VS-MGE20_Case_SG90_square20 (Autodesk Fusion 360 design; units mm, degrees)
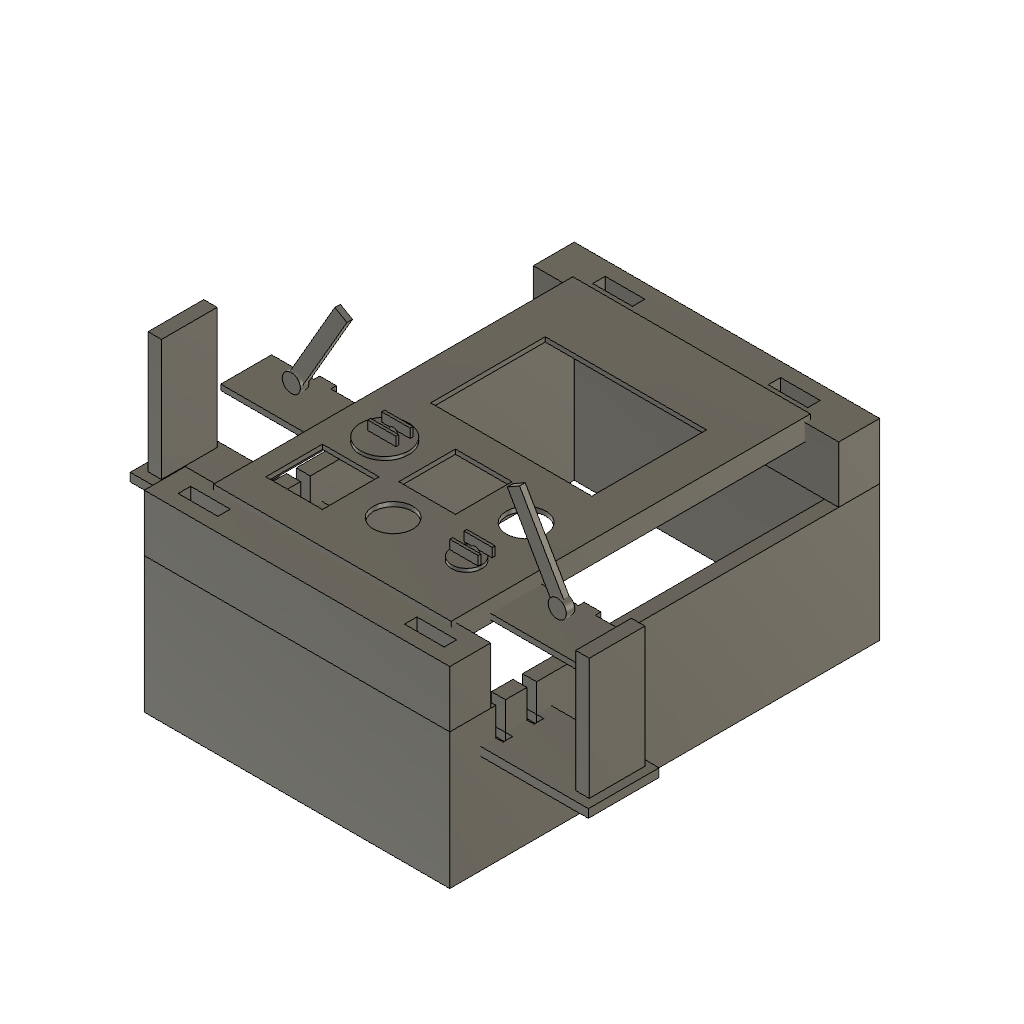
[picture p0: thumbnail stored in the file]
sketch "スケッチ1" plane through (0, 0, 0) normal (0, 0, 1) x axis (1, 0, 0)
  line L1 (42, -63.5) -> (-42, -63.5)
  line L2 (42, 63.5) -> (42, -63.5)
  line L3 (-42, 63.5) -> (42, 63.5)
  line L4 (-42, -63.5) -> (-42, 63.5)
  line L5 (28.5, -0.25) -> (-28.5, -0.25)
  line L6 (28.5, 40.25) -> (28.5, -0.25)
  line L7 (-28.5, 40.25) -> (28.5, 40.25)
  line L8 (-28.5, -0.25) -> (-28.5, 40.25)
  line L9 (-16, -34.55) -> (-33, -34.55)
  line L10 (-16, -33.45) -> (-16, -34.55)
  line L11 (-33, -33.45) -> (-16, -33.45)
  line L12 (-33, -34.55) -> (-33, -33.45)
  line L13 (-16, -37.55) -> (-33, -37.55)
  line L14 (-16, -36.45) -> (-16, -37.55)
  line L15 (-33, -36.45) -> (-16, -36.45)
  line L16 (-33, -37.55) -> (-33, -36.45)
  line L17 (-16, -40.55) -> (-33, -40.55)
  line L18 (-16, -39.45) -> (-16, -40.55)
  line L19 (-33, -39.45) -> (-16, -39.45)
  line L20 (-33, -40.55) -> (-33, -39.45)
  line L21 (-16, -43.55) -> (-33, -43.55)
  line L22 (-16, -42.45) -> (-16, -43.55)
  line L23 (-33, -42.45) -> (-16, -42.45)
  line L24 (-33, -43.55) -> (-33, -42.45)
  line L25 (-16, -46.55) -> (-33, -46.55)
  line L26 (-16, -45.45) -> (-16, -46.55)
  line L27 (-33, -45.45) -> (-16, -45.45)
  line L28 (-33, -46.55) -> (-33, -45.45)
  line L29 (-16, -49.55) -> (-33, -49.55)
  line L30 (-16, -48.45) -> (-16, -49.55)
  line L31 (-33, -48.45) -> (-16, -48.45)
  line L32 (-33, -49.55) -> (-33, -48.45)
  circle C1 centre (-25, -20) radius 8
  circle C2 centre (26, -42) radius 4.8
extrude "押し出し1" new body sketch "スケッチ1" along normal blind 1.6
sketch "スケッチ2" plane through (0, 0, 0) normal (0, 0, 1) x axis (1, 0, 0)
  line L1 (42, -63.5) -> (-42, -63.5)
  line L2 (42, 63.5) -> (42, -63.5)
  line L3 (-42, 63.5) -> (42, 63.5)
  line L4 (-42, -63.5) -> (-42, 63.5)
  line L5 (40.5, -62) -> (-40.5, -62)
  line L6 (40.5, 62) -> (40.5, -62)
  line L7 (-40.5, 62) -> (40.5, 62)
  line L8 (-40.5, -62) -> (-40.5, 62)
extrude "押し出し4" add sketch "スケッチ2" against normal blind 6 (magnitude of "-( 6.00 mm )")
work_plane "作業平面1" AlongDistance -68 ExtraOffset 0
sketch "スケッチ3" plane through (0, 0, -68) normal (0, 0, 1) x axis (1, 0, 0)
  line L1 (54, -76) -> (-54, -76)
  line L2 (54, 76) -> (54, -76)
  line L3 (-54, 76) -> (54, 76)
  line L4 (-54, -76) -> (-54, 76)
  line L5 (49, -71) -> (-49, -71)
  line L6 (49, 71) -> (49, -71)
  line L7 (-49, 71) -> (49, 71)
  line L8 (-49, -71) -> (-49, 71)
work_plane "作業平面2" AlongDistance -20 ExtraOffset 0
sketch "スケッチ4" plane through (0, 0, -20) normal (0, 0, 1) x axis (1, 0, 0)
  line L1 (54, 61.5) -> (-54, 61.5)
  line L2 (54, 76) -> (54, 61.5)
  line L3 (-54, 76) -> (54, 76)
  line L4 (-54, 61.5) -> (-54, 76)
  line L5 (54, -76) -> (-54, -76)
  line L6 (54, -61.5) -> (54, -76)
  line L7 (-54, -61.5) -> (54, -61.5)
  line L8 (-54, -76) -> (-54, -61.5)
extrude "押し出し6" new body sketch "スケッチ4" profile of L1 L2 L3 L4 along normal blind 20
work_plane "作業平面3" AlongDistance -23 ExtraOffset 0
sketch "スケッチ5" plane through (0, 0, -23) normal (0, 0, 1) x axis (1, 0, 0)
  line L1 (-44, -24) -> (-90, -24)
  line L2 (-44, 28) -> (-44, -24)
  line L3 (-90, 28) -> (-44, 28)
  line L4 (-90, -24) -> (-90, 28)
  line L5 (90, -46) -> (44, -46)
  line L6 (90, 6) -> (90, -46)
  line L7 (44, 6) -> (90, 6)
  line L8 (44, -46) -> (44, 6)
  circle C1 centre (-84, -18) radius 1.7
  circle C2 centre (-50, 20) radius 1.7
  circle C3 centre (-84, -56) radius 1.7
  circle C4 centre (-50, -22) radius 1.7
  circle C5 centre (84, -40) radius 1.7
  circle C6 centre (50, 2) radius 1.7
  circle C7 centre (84, -78) radius 1.7
  circle C8 centre (50, -44) radius 1.7
work_plane "作業平面4" AlongDistance -20 ExtraOffset 0
sketch "スケッチ6" plane through (0, 0, -20) normal (0, 0, 1) x axis (1, 0, 0)
  line L1 (54, -76) -> (-54, -76)
  line L2 (54, -61.5) -> (54, -76)
  line L3 (-54, -61.5) -> (54, -61.5)
  line L4 (-54, -76) -> (-54, -61.5)
work_plane "作業平面5" AlongDistance -23 ExtraOffset 0
sketch "スケッチ7" plane through (0, 0, -23) normal (0, 0, 1) x axis (1, 0, 0)
  line L1 (90, -46) -> (44, -46)
  line L2 (90, 6) -> (90, -46)
  line L3 (44, 6) -> (90, 6)
  line L4 (44, -46) -> (44, 6)
  circle C1 centre (84, -40) radius 1.7
  circle C2 centre (50, 2) radius 1.7
  circle C3 centre (84, -78) radius 1.7
  circle C4 centre (50, -44) radius 1.7
work_plane "作業平面6" AlongDistance -19.7 ExtraOffset 0
sketch "スケッチ8" plane through (0, 0, -19.7) normal (0, 0, 1) x axis (1, 0, 0)
  line L1 (-46.65, -20) -> (-87.35, -20)
  line L2 (-46.65, 22.9) -> (-46.65, -20)
  line L3 (-87.35, 22.9) -> (-46.65, 22.9)
  line L4 (-87.35, -20) -> (-87.35, 22.9)
work_plane "作業平面7" AlongDistance -19.7 ExtraOffset 0
sketch "スケッチ9" plane through (0, 0, -19.7) normal (0, 0, 1) x axis (1, 0, 0)
  line L1 (87.35, -42) -> (46.65, -42)
  line L2 (87.35, 0.9) -> (87.35, -42)
  line L3 (46.65, 0.9) -> (87.35, 0.9)
  line L4 (46.65, -42) -> (46.65, 0.9)
work_plane "作業平面8" AlongDistance 18 ExtraOffset 0
sketch "スケッチ10" plane through (0, 18, 0) normal (0, 1, 0) x axis (1, 0, 0)
  line L1 (-25.3119, 0.9501) -> (-55.3119, -8.8999)
  line L2 (-24.6881, -0.9501) -> (-25.3119, 0.9501)
  line L3 (-54.6881, -10.8001) -> (-24.6881, -0.9501)
  line L4 (-55.3119, -8.8999) -> (-54.6881, -10.8001)
work_plane "作業平面9" AlongDistance 40 ExtraOffset 0
sketch "スケッチ11" plane through (0, 40, 0) normal (0, 1, 0) x axis (1, 0, 0)
  line L1 (25.6784, -0.9469) -> (54.6784, -10.7969)
  line L2 (26.3216, 0.9469) -> (25.6784, -0.9469)
  line L3 (55.3216, -8.9031) -> (26.3216, 0.9469)
  line L4 (54.6784, -10.7969) -> (55.3216, -8.9031)
work_plane "作業平面10" AlongDistance -0.3 ExtraOffset 0
sketch "スケッチ12" plane through (0, 0, -0.3) normal (0, 0, 1) x axis (1, 0, 0)
  circle C1 centre (-25, -20) radius 3.5
  circle C2 centre (26, -42) radius 2.8
work_plane "作業平面11" AlongDistance 1.6 ExtraOffset 0
sketch "スケッチ13" plane through (0, 0, 1.6) normal (0, 0, 1) x axis (1, 0, 0)
  line L1 (-24.6696, -17.5219) -> (-54.6696, -13.5219)
  line L2 (-25.3304, -22.4781) -> (-24.6696, -17.5219)
  line L3 (-55.3304, -18.4781) -> (-25.3304, -22.4781)
  line L4 (-54.6696, -13.5219) -> (-55.3304, -18.4781)
  line L5 (26.3416, -44.4766) -> (55.3416, -40.4766)
  line L6 (25.6584, -39.5234) -> (26.3416, -44.4766)
  line L7 (54.6584, -35.5234) -> (25.6584, -39.5234)
  line L8 (55.3416, -40.4766) -> (54.6584, -35.5234)
work_plane "作業平面12" AlongDistance 0 ExtraOffset 0
sketch "スケッチ14" plane through (0, 0, 0) normal (0, 0, 1) x axis (1, 0, 0)
  circle C1 centre (-55, -16) radius 4.2
  circle C2 centre (55, -38) radius 4.2
work_plane "作業平面13" AlongDistance -0.3 ExtraOffset 0
sketch "スケッチ15" plane through (0, 0, -0.3) normal (0, 0, 1) x axis (1, 0, 0)
  circle C1 centre (-25, -20) radius 3.5
  circle C2 centre (26, -42) radius 2.8
work_plane "作業平面14" AlongDistance -20 ExtraOffset 0
sketch "スケッチ16" plane through (0, 0, -20) normal (0, 0, 1) x axis (1, 0, 0)
  line L1 (-24, -70.95) -> (-38, -70.95)
  line L2 (-24, -66.55) -> (-24, -70.95)
  line L3 (-38, -66.55) -> (-24, -66.55)
  line L4 (-38, -70.95) -> (-38, -66.55)
  line L5 (38, -70.95) -> (24, -70.95)
  line L6 (38, -66.55) -> (38, -70.95)
  line L7 (24, -66.55) -> (38, -66.55)
  line L8 (24, -70.95) -> (24, -66.55)
  line L9 (-24, 66.55) -> (-38, 66.55)
  line L10 (-24, 70.95) -> (-24, 66.55)
  line L11 (-38, 70.95) -> (-24, 70.95)
  line L12 (-38, 66.55) -> (-38, 70.95)
  line L13 (38, 66.55) -> (24, 66.55)
  line L14 (38, 70.95) -> (38, 66.55)
  line L15 (24, 70.95) -> (38, 70.95)
  line L16 (24, 66.55) -> (24, 70.95)
work_plane "作業平面15" AlongDistance 1.6 ExtraOffset 0
sketch "スケッチ17" plane through (0, 0, 1.6) normal (0, 0, 1) x axis (1, 0, 0)
  line L1 (26.3416, -44.4766) -> (55.3416, -40.4766)
  line L2 (25.6584, -39.5234) -> (26.3416, -44.4766)
  line L3 (54.6584, -35.5234) -> (25.6584, -39.5234)
  line L4 (55.3416, -40.4766) -> (54.6584, -35.5234)
work_plane "作業平面16" AlongDistance 0 ExtraOffset 0
sketch "スケッチ18" plane through (0, 0, 0) normal (0, 0, 1) x axis (1, 0, 0)
  circle C1 centre (55, -38) radius 4.2
work_plane "作業平面17" AlongDistance -0.3 ExtraOffset 0
sketch "スケッチ19" plane through (0, 0, -0.3) normal (0, 0, 1) x axis (1, 0, 0)
  circle C1 centre (26, -42) radius 2.8
work_plane "作業平面18" AlongDistance -20 ExtraOffset 0
sketch "スケッチ20" plane through (0, 0, -20) normal (0, 0, 1) x axis (1, 0, 0)
  line L1 (38, -70.95) -> (24, -70.95)
  line L2 (38, -66.55) -> (38, -70.95)
  line L3 (24, -66.55) -> (38, -66.55)
  line L4 (24, -70.95) -> (24, -66.55)
work_plane "作業平面19" AlongDistance -20 ExtraOffset 0
sketch "スケッチ21" plane through (0, 0, -20) normal (0, 0, 1) x axis (1, 0, 0)
  line L1 (-24, 66.55) -> (-38, 66.55)
  line L2 (-24, 70.95) -> (-24, 66.55)
  line L3 (-38, 70.95) -> (-24, 70.95)
  line L4 (-38, 66.55) -> (-38, 70.95)
extrude "押し出し24" cut sketch "スケッチ21" along normal blind 22
work_plane "作業平面20" AlongDistance -20 ExtraOffset 0
sketch "スケッチ22" plane through (0, 0, -20) normal (0, 0, 1) x axis (1, 0, 0)
  line L1 (38, 66.55) -> (24, 66.55)
  line L2 (38, 70.95) -> (38, 66.55)
  line L3 (24, 70.95) -> (38, 70.95)
  line L4 (24, 66.55) -> (24, 70.95)
extrude "押し出し25" cut sketch "スケッチ22" along normal blind 22
work_plane "作業平面21" AlongDistance -0.3 ExtraOffset 0
sketch "スケッチ23" plane through (0, 0, -0.3) normal (0, 0, 1) x axis (1, 0, 0)
  circle C1 centre (-25, -20) radius 3.5
work_plane "作業平面22" AlongDistance -0.3 ExtraOffset 0
sketch "スケッチ24" plane through (0, 0, -0.3) normal (0, 0, 1) x axis (1, 0, 0)
  circle C1 centre (26, -42) radius 2.8
work_plane "作業平面23" AlongDistance 1.6 ExtraOffset 0
sketch "スケッチ25" plane through (0, 0, 1.6) normal (0, 0, 1) x axis (1, 0, 0)
  circle C1 centre (-25, -20) radius 8.5
work_plane "作業平面24" AlongDistance 1.6 ExtraOffset 0
sketch "スケッチ26" plane through (0, 0, 1.6) normal (0, 0, 1) x axis (1, 0, 0)
  circle C1 centre (26, -42) radius 5.3
work_plane "作業平面25" AlongDistance -33 ExtraOffset 0
sketch "スケッチ27" plane through (0, 0, -33) normal (0, 0, 1) x axis (1, 0, 0)
  line L1 (-42, -43) -> (-92, -43)
  line L2 (-42, -18) -> (-42, -43)
  line L3 (-92, -18) -> (-42, -18)
  line L4 (-92, -43) -> (-92, -18)
work_plane "作業平面26" AlongDistance -33 ExtraOffset 0
sketch "スケッチ28" plane through (0, 0, -33) normal (0, 0, 1) x axis (1, 0, 0)
  line L1 (-86.3, -41) -> (-89.7, -41)
  line L2 (-86.3, -34) -> (-86.3, -41)
  line L3 (-89.7, -34) -> (-86.3, -34)
  line L4 (-89.7, -41) -> (-89.7, -34)
  line L5 (-86.3, -27) -> (-89.7, -27)
  line L6 (-86.3, -20) -> (-86.3, -27)
  line L7 (-89.7, -20) -> (-86.3, -20)
  line L8 (-89.7, -27) -> (-89.7, -20)
  line L9 (-44.3, -41) -> (-47.7, -41)
  line L10 (-44.3, -34) -> (-44.3, -41)
  line L11 (-47.7, -34) -> (-44.3, -34)
  line L12 (-47.7, -41) -> (-47.7, -34)
  line L13 (-44.3, -27) -> (-47.7, -27)
  line L14 (-44.3, -20) -> (-44.3, -27)
  line L15 (-47.7, -20) -> (-44.3, -20)
  line L16 (-47.7, -27) -> (-47.7, -20)
work_plane "作業平面27" AlongDistance -30 ExtraOffset 0
sketch "スケッチ29" plane through (0, 0, -30) normal (0, 0, 1) x axis (1, 0, 0)
  line L1 (-87, -40.7) -> (-92, -40.7)
  line L2 (-87, -19) -> (-87, -40.7)
  line L3 (-92, -19) -> (-87, -19)
  line L4 (-92, -40.7) -> (-92, -19)
work_plane "作業平面28" AlongDistance -30 ExtraOffset 0
sketch "スケッチ30" plane through (0, 0, -30) normal (0, 0, 1) x axis (1, 0, 0)
  line L1 (-43.5, -40.7) -> (-46.5, -40.7)
  line L2 (-43.5, -19) -> (-43.5, -40.7)
  line L3 (-46.5, -19) -> (-43.5, -19)
  line L4 (-46.5, -40.7) -> (-46.5, -19)
work_plane "作業平面29" AlongDistance -30 ExtraOffset 0
sketch "スケッチ31" plane through (0, 0, -30) normal (0, 0, 1) x axis (1, 0, 0)
  line L1 (-43.5, -39.7) -> (-84.2, -39.7)
  line L2 (-43.5, -20) -> (-43.5, -39.7)
  line L3 (-84.2, -20) -> (-43.5, -20)
  line L4 (-84.2, -39.7) -> (-84.2, -20)
extrude "押し出し37" new body sketch "スケッチ31" along normal blind 42.9
work_plane "作業平面30" AlongDistance 20 ExtraOffset 0
sketch "スケッチ32" plane through (0, 20, 0) normal (0, 1, 0) x axis (1, 0, 0)
  circle C1 centre (-58, 2.8) radius 3.2
work_plane "作業平面31" AlongDistance 18.5 ExtraOffset 0
sketch "スケッチ33" plane through (0, 18.5, 0) normal (0, 1, 0) x axis (1, 0, 0)
  line L1 (-43.6651, 32.63) -> (-60.1651, 4.05)
  line L2 (-39.3349, 30.13) -> (-43.6651, 32.63)
  line L3 (-55.8349, 1.55) -> (-39.3349, 30.13)
  line L4 (-60.1651, 4.05) -> (-55.8349, 1.55)
work_plane "作業平面32" AlongDistance 18.5 ExtraOffset 0
sketch "スケッチ34" plane through (0, 18.5, 0) normal (0, 1, 0) x axis (1, 0, 0)
  line L1 (-25, 5.3) -> (-58, 5.3)
  line L2 (-25, 0.3) -> (-25, 5.3)
  line L3 (-58, 0.3) -> (-25, 0.3)
  line L4 (-58, 5.3) -> (-58, 0.3)
work_plane "作業平面33" AlongDistance -0.3 ExtraOffset 0
sketch "スケッチ35" plane through (0, 0, -0.3) normal (0, 0, 1) x axis (1, 0, 0)
  circle C1 centre (-25, -20) radius 3.5
extrude "押し出し41" new body sketch "スケッチ35" along normal blind 1.9
work_plane "作業平面34" AlongDistance 1.6 ExtraOffset 0
sketch "スケッチ36" plane through (0, 0, 1.6) normal (0, 0, 1) x axis (1, 0, 0)
  circle C1 centre (-25, -20) radius 8.5
extrude "押し出し42" new body sketch "スケッチ36" along normal blind 1.2
work_plane "作業平面35" AlongDistance 0 ExtraOffset 0
sketch "スケッチ37" plane through (0, 0, 0) normal (0, 0, 1) x axis (1, 0, 0)
  circle C1 centre (-25, -20) radius 7
  circle C2 centre (-25, -20) radius 3.8
extrude "押し出し43" new body sketch "スケッチ37" along normal blind 1.6
work_plane "作業平面36" AlongDistance 2.8 ExtraOffset 0
sketch "スケッチ38" plane through (0, 0, 2.8) normal (0, 0, 1) x axis (1, 0, 0)
  line L1 (-20, -23.8) -> (-30, -23.8)
  line L2 (-20, -22.6) -> (-20, -23.8)
  line L3 (-30, -22.6) -> (-20, -22.6)
  line L4 (-30, -23.8) -> (-30, -22.6)
  line L5 (-20, -17.4) -> (-30, -17.4)
  line L6 (-20, -16.2) -> (-20, -17.4)
  line L7 (-30, -16.2) -> (-20, -16.2)
  line L8 (-30, -17.4) -> (-30, -16.2)
work_plane "作業平面37" AlongDistance -33 ExtraOffset 0
sketch "スケッチ39" plane through (0, 0, -33) normal (0, 0, 1) x axis (1, 0, 0)
  line L1 (92, -65) -> (42, -65)
  line L2 (92, -40) -> (92, -65)
  line L3 (42, -40) -> (92, -40)
  line L4 (42, -65) -> (42, -40)
work_plane "作業平面38" AlongDistance -33 ExtraOffset 0
sketch "スケッチ40" plane through (0, 0, -33) normal (0, 0, 1) x axis (1, 0, 0)
  line L1 (47.7, -63) -> (44.3, -63)
  line L2 (47.7, -56) -> (47.7, -63)
  line L3 (44.3, -56) -> (47.7, -56)
  line L4 (44.3, -63) -> (44.3, -56)
  line L5 (47.7, -49) -> (44.3, -49)
  line L6 (47.7, -42) -> (47.7, -49)
  line L7 (44.3, -42) -> (47.7, -42)
  line L8 (44.3, -49) -> (44.3, -42)
  line L9 (89.7, -63) -> (86.3, -63)
  line L10 (89.7, -56) -> (89.7, -63)
  line L11 (86.3, -56) -> (89.7, -56)
  line L12 (86.3, -63) -> (86.3, -56)
  line L13 (89.7, -49) -> (86.3, -49)
  line L14 (89.7, -42) -> (89.7, -49)
  line L15 (86.3, -42) -> (89.7, -42)
  line L16 (86.3, -49) -> (86.3, -42)
work_plane "作業平面39" AlongDistance -30 ExtraOffset 0
sketch "スケッチ41" plane through (0, 0, -30) normal (0, 0, 1) x axis (1, 0, 0)
  line L1 (47, -62.7) -> (42, -62.7)
  line L2 (47, -41) -> (47, -62.7)
  line L3 (42, -41) -> (47, -41)
  line L4 (42, -62.7) -> (42, -41)
work_plane "作業平面40" AlongDistance -30 ExtraOffset 0
sketch "スケッチ42" plane through (0, 0, -30) normal (0, 0, 1) x axis (1, 0, 0)
  line L1 (90.5, -62.7) -> (87.5, -62.7)
  line L2 (90.5, -41) -> (90.5, -62.7)
  line L3 (87.5, -41) -> (90.5, -41)
  line L4 (87.5, -62.7) -> (87.5, -41)
work_plane "作業平面41" AlongDistance -30 ExtraOffset 0
sketch "スケッチ43" plane through (0, 0, -30) normal (0, 0, 1) x axis (1, 0, 0)
  line L1 (84.2, -61.7) -> (43.5, -61.7)
  line L2 (84.2, -42) -> (84.2, -61.7)
  line L3 (43.5, -42) -> (84.2, -42)
  line L4 (43.5, -61.7) -> (43.5, -42)
extrude "押し出し53" new body sketch "スケッチ43" along normal blind 42.9
work_plane "作業平面42" AlongDistance 42 ExtraOffset 0
sketch "スケッチ44" plane through (0, 42, 0) normal (0, 1, 0) x axis (1, 0, 0)
  circle C1 centre (58, 2.8) radius 3.2
work_plane "作業平面43" AlongDistance 40.5 ExtraOffset 0
sketch "スケッチ45" plane through (0, 40.5, 0) normal (0, 1, 0) x axis (1, 0, 0)
  line L1 (39.835, 29.2599) -> (55.835, 1.5499)
  line L2 (44.165, 31.7601) -> (39.835, 29.2599)
  line L3 (60.165, 4.0501) -> (44.165, 31.7601)
  line L4 (55.835, 1.5499) -> (60.165, 4.0501)
work_plane "作業平面44" AlongDistance 40.5 ExtraOffset 0
sketch "スケッチ46" plane through (0, 40.5, 0) normal (0, 1, 0) x axis (1, 0, 0)
  line L1 (26, 0.3) -> (58, 0.3)
  line L2 (26, 5.3) -> (26, 0.3)
  line L3 (58, 5.3) -> (26, 5.3)
  line L4 (58, 0.3) -> (58, 5.3)
work_plane "作業平面45" AlongDistance -0.3 ExtraOffset 0
sketch "スケッチ47" plane through (0, 0, -0.3) normal (0, 0, 1) x axis (1, 0, 0)
  circle C1 centre (26, -42) radius 2.8
extrude "押し出し57" new body sketch "スケッチ47" along normal blind 1.9
work_plane "作業平面46" AlongDistance 1.6 ExtraOffset 0
sketch "スケッチ48" plane through (0, 0, 1.6) normal (0, 0, 1) x axis (1, 0, 0)
  circle C1 centre (26, -42) radius 5.3
extrude "押し出し58" new body sketch "スケッチ48" along normal blind 1.2
work_plane "作業平面47" AlongDistance 0 ExtraOffset 0
sketch "スケッチ49" plane through (0, 0, 0) normal (0, 0, 1) x axis (1, 0, 0)
  circle C1 centre (26, -42) radius 4.2
  circle C2 centre (26, -42) radius 3
extrude "押し出し59" new body sketch "スケッチ49" along normal blind 1.6
work_plane "作業平面48" AlongDistance 2.8 ExtraOffset 0
sketch "スケッチ50" plane through (0, 0, 2.8) normal (0, 0, 1) x axis (1, 0, 0)
  line L1 (31, -45.8) -> (21, -45.8)
  line L2 (31, -44.6) -> (31, -45.8)
  line L3 (21, -44.6) -> (31, -44.6)
  line L4 (21, -45.8) -> (21, -44.6)
  line L5 (31, -39.4) -> (21, -39.4)
  line L6 (31, -38.2) -> (31, -39.4)
  line L7 (21, -38.2) -> (31, -38.2)
  line L8 (21, -39.4) -> (21, -38.2)
work_plane "作業平面49" AlongDistance -20 ExtraOffset 0
sketch "スケッチ51" plane through (0, -20, 0) normal (0, 1, 0) x axis (1, 0, 0)
  circle C1 centre (-58, -2.8) radius 3.2
work_plane "作業平面50" AlongDistance -18.5 ExtraOffset 0
sketch "スケッチ52" plane through (0, -18.5, 0) normal (0, 1, 0) x axis (1, 0, 0)
  line L1 (-43.6655, -32.6493) -> (-60.1655, -4.0493)
  line L2 (-39.3345, -30.1507) -> (-43.6655, -32.6493)
  line L3 (-55.8345, -1.5507) -> (-39.3345, -30.1507)
  line L4 (-60.1655, -4.0493) -> (-55.8345, -1.5507)
work_plane "作業平面51" AlongDistance -18.5 ExtraOffset 0
sketch "スケッチ53" plane through (0, -18.5, 0) normal (0, 1, 0) x axis (1, 0, 0)
  line L1 (-25, -5.3) -> (-58, -5.3)
  line L2 (-25, -0.3) -> (-25, -5.3)
  line L3 (-58, -0.3) -> (-25, -0.3)
  line L4 (-58, -5.3) -> (-58, -0.3)
work_plane "作業平面52" AlongDistance -42 ExtraOffset 0
sketch "スケッチ54" plane through (0, -42, 0) normal (0, 1, 0) x axis (1, 0, 0)
  circle C1 centre (58, -2.8) radius 3.2
work_plane "作業平面53" AlongDistance -40.5 ExtraOffset 0
sketch "スケッチ55" plane through (0, -40.5, 0) normal (0, 1, 0) x axis (1, 0, 0)
  line L1 (39.3345, -30.1507) -> (55.8345, -1.5507)
  line L2 (43.6655, -32.6493) -> (39.3345, -30.1507)
  line L3 (60.1655, -4.0493) -> (43.6655, -32.6493)
  line L4 (55.8345, -1.5507) -> (60.1655, -4.0493)
work_plane "作業平面54" AlongDistance -40.5 ExtraOffset 0
sketch "スケッチ56" plane through (0, -40.5, 0) normal (0, 1, 0) x axis (1, 0, 0)
  line L1 (26, -0.3) -> (58, -0.3)
  line L2 (26, -5.3) -> (26, -0.3)
  line L3 (58, -5.3) -> (26, -5.3)
  line L4 (58, -0.3) -> (58, -5.3)
work_plane "作業平面55" AlongDistance -30 ExtraOffset 0
sketch "スケッチ57" plane through (0, 0, -30) normal (0, 0, 1) x axis (1, 0, 0)
  line L1 (-84.2, -39.7) -> (-89, -39.7)
  line L2 (-84.2, -20) -> (-84.2, -39.7)
  line L3 (-89, -20) -> (-84.2, -20)
  line L4 (-89, -39.7) -> (-89, -20)
extrude "押し出し68" new body sketch "スケッチ57" along normal blind 42.9
work_plane "作業平面56" AlongDistance -20 ExtraOffset 0
sketch "スケッチ58" plane through (0, -20, 0) normal (0, 1, 0) x axis (1, 0, 0)
  circle C1 centre (-58, -2.8) radius 3.2
extrude "押し出し69" new body sketch "スケッチ58" along normal blind 3
work_plane "作業平面57" AlongDistance -17 ExtraOffset 0
sketch "スケッチ59" plane through (0, -17, 0) normal (0, 1, 0) x axis (1, 0, 0)
  line L1 (-43.6655, -32.6493) -> (-60.1655, -4.0493)
  line L2 (-39.3345, -30.1507) -> (-43.6655, -32.6493)
  line L3 (-55.8345, -1.5507) -> (-39.3345, -30.1507)
  line L4 (-60.1655, -4.0493) -> (-55.8345, -1.5507)
extrude "押し出し70" new body sketch "スケッチ59" against normal blind 2 (magnitude of "-( 2.00 mm )")
work_plane "作業平面58" AlongDistance -17 ExtraOffset 0
sketch "スケッチ60" plane through (0, -17, 0) normal (0, 1, 0) x axis (1, 0, 0)
  line L1 (-25, -5.3) -> (-58, -5.3)
  line L2 (-25, -0.3) -> (-25, -5.3)
  line L3 (-58, -0.3) -> (-25, -0.3)
  line L4 (-58, -5.3) -> (-58, -0.3)
extrude "押し出し71" new body sketch "スケッチ60" against normal blind 2 (magnitude of "-( 2.00 mm )")
work_plane "作業平面59" AlongDistance 2.8 ExtraOffset 0
sketch "スケッチ61" plane through (0, 0, 2.8) normal (0, 0, 1) x axis (1, 0, 0)
  line L1 (-20, -21) -> (-30, -21)
  line L2 (-20, -20) -> (-20, -21)
  line L3 (-30, -20) -> (-20, -20)
  line L4 (-30, -21) -> (-30, -20)
  line L5 (-20, -16) -> (-30, -16)
  line L6 (-20, -15) -> (-20, -16)
  line L7 (-30, -15) -> (-20, -15)
  line L8 (-30, -16) -> (-30, -15)
extrude "押し出し72" new body sketch "スケッチ61" profile of L1 L2 L3 L4 along normal blind 3.2
extrude "押し出し73" new body sketch "スケッチ61" profile of L5 L6 L7 L8 along normal blind 3.2
work_plane "作業平面60" AlongDistance -30 ExtraOffset 0
sketch "スケッチ62" plane through (0, 0, -30) normal (0, 0, 1) x axis (1, 0, 0)
  line L1 (89, -61.7) -> (84.2, -61.7)
  line L2 (89, -42) -> (89, -61.7)
  line L3 (84.2, -42) -> (89, -42)
  line L4 (84.2, -61.7) -> (84.2, -42)
extrude "押し出し74" new body sketch "スケッチ62" along normal blind 42.9
work_plane "作業平面61" AlongDistance -42 ExtraOffset 0
sketch "スケッチ63" plane through (0, -42, 0) normal (0, 1, 0) x axis (1, 0, 0)
  circle C1 centre (58, -2.8) radius 3.2
extrude "押し出し75" new body sketch "スケッチ63" along normal blind 3
work_plane "作業平面62" AlongDistance -39 ExtraOffset 0
sketch "スケッチ64" plane through (0, -39, 0) normal (0, 1, 0) x axis (1, 0, 0)
  line L1 (39.3345, -30.1507) -> (55.8345, -1.5507)
  line L2 (43.6655, -32.6493) -> (39.3345, -30.1507)
  line L3 (60.1655, -4.0493) -> (43.6655, -32.6493)
  line L4 (55.8345, -1.5507) -> (60.1655, -4.0493)
extrude "押し出し76" new body sketch "スケッチ64" against normal blind 2 (magnitude of "-( 2.00 mm )")
work_plane "作業平面63" AlongDistance -39 ExtraOffset 0
sketch "スケッチ65" plane through (0, -39, 0) normal (0, 1, 0) x axis (1, 0, 0)
  line L1 (26, -0.3) -> (58, -0.3)
  line L2 (26, -5.3) -> (26, -0.3)
  line L3 (58, -5.3) -> (26, -5.3)
  line L4 (58, -0.3) -> (58, -5.3)
extrude "押し出し77" new body sketch "スケッチ65" against normal blind 2 (magnitude of "-( 2.00 mm )")
work_plane "作業平面64" AlongDistance 2.8 ExtraOffset 0
sketch "スケッチ66" plane through (0, 0, 2.8) normal (0, 0, 1) x axis (1, 0, 0)
  line L1 (31, -43) -> (21, -43)
  line L2 (31, -42) -> (31, -43)
  line L3 (21, -42) -> (31, -42)
  line L4 (21, -43) -> (21, -42)
  line L5 (31, -38) -> (21, -38)
  line L6 (31, -37) -> (31, -38)
  line L7 (21, -37) -> (31, -37)
  line L8 (21, -38) -> (21, -37)
extrude "押し出し78" new body sketch "スケッチ66" profile of L1 L2 L3 L4 along normal blind 3.2
extrude "押し出し79" new body sketch "スケッチ66" profile of L5 L6 L7 L8 along normal blind 3.2
work_plane "作業平面65" AlongDistance -33 ExtraOffset 0
sketch "スケッチ67" plane through (0, 0, -33) normal (0, 0, 1) x axis (1, 0, 0)
  circle C1 centre (-51.5, -37) radius 17
  circle C2 centre (-51.5, -24) radius 17
  circle C3 centre (51.5, -58) radius 17
  circle C4 centre (51.5, -47) radius 17
work_plane "作業平面66" AlongDistance -19 ExtraOffset 0
sketch "スケッチ68" plane through (0, -19, 0) normal (0, 1, 0) x axis (1, 0, 0)
  circle C1 centre (-25, -2.8) radius 15
work_plane "作業平面67" AlongDistance -41 ExtraOffset 0
sketch "スケッチ69" plane through (0, -41, 0) normal (0, 1, 0) x axis (1, 0, 0)
  circle C1 centre (26, -2.8) radius 15
work_plane "作業平面68" AlongDistance -1.1 ExtraOffset 0
sketch "スケッチ70" plane through (0, 0, -1.1) normal (0, 0, 1) x axis (1, 0, 0)
  circle C1 centre (-25, -20) radius 3.5
extrude "押し出し88" new body sketch "スケッチ70" along normal blind 0.8
work_plane "作業平面69" AlongDistance -1.1 ExtraOffset 0
sketch "スケッチ71" plane through (0, 0, -1.1) normal (0, 0, 1) x axis (1, 0, 0)
  circle C1 centre (26, -42) radius 2.8
extrude "押し出し89" new body sketch "スケッチ71" along normal blind 0.8
work_plane "作業平面70" AlongDistance -68 ExtraOffset 0
sketch "スケッチ72" plane through (0, 0, -68) normal (0, 0, 1) x axis (1, 0, 0)
  line L1 (54, -76) -> (-54, -76)
  line L2 (54, 76) -> (54, -76)
  line L3 (-54, 76) -> (54, 76)
  line L4 (-54, -76) -> (-54, 76)
  line L5 (49, -71) -> (-49, -71)
  line L6 (49, 71) -> (49, -71)
  line L7 (-49, 71) -> (49, 71)
  line L8 (-49, -71) -> (-49, 71)
work_plane "作業平面71" AlongDistance -20 ExtraOffset 0
sketch "スケッチ73" plane through (0, 0, -20) normal (0, 0, 1) x axis (1, 0, 0)
  line L1 (54, -76) -> (-54, -76)
  line L2 (54, -61.5) -> (54, -76)
  line L3 (-54, -61.5) -> (54, -61.5)
  line L4 (-54, -76) -> (-54, -61.5)
  line L5 (-33, -71) -> (-47, -71)
  line L6 (-33, -66.6) -> (-33, -71)
  line L7 (-47, -66.6) -> (-33, -66.6)
  line L8 (-47, -71) -> (-47, -66.6)
  line L9 (7, -71) -> (-7, -71)
  line L10 (7, -66.6) -> (7, -71)
  line L11 (-7, -66.6) -> (7, -66.6)
  line L12 (-7, -71) -> (-7, -66.6)
  line L13 (47, -71) -> (33, -71)
  line L14 (47, -66.6) -> (47, -71)
  line L15 (33, -66.6) -> (47, -66.6)
  line L16 (33, -71) -> (33, -66.6)
  line L17 (-33, -63.5) -> (-47, -63.5)
  line L18 (-33, -59.1) -> (-33, -63.5)
  line L19 (-47, -59.1) -> (-33, -59.1)
  line L20 (-47, -63.5) -> (-47, -59.1)
work_plane "作業平面72" AlongDistance -33 ExtraOffset 0
sketch "スケッチ74" plane through (0, 0, -33) normal (0, 0, 1) x axis (1, 0, 0)
  line L1 (-42, -43) -> (-92, -43)
  line L2 (-42, -18) -> (-42, -43)
  line L3 (-92, -18) -> (-42, -18)
  line L4 (-92, -43) -> (-92, -18)
  line L5 (-48.5, -38.7) -> (-56.5, -38.7)
  line L6 (-48.5, -35.3) -> (-48.5, -38.7)
  line L7 (-56.5, -35.3) -> (-48.5, -35.3)
  line L8 (-56.5, -38.7) -> (-56.5, -35.3)
  line L9 (-48.5, -25.7) -> (-56.5, -25.7)
  line L10 (-48.5, -22.3) -> (-48.5, -25.7)
  line L11 (-56.5, -22.3) -> (-48.5, -22.3)
  line L12 (-56.5, -25.7) -> (-56.5, -22.3)
extrude "押し出し92" new body sketch "スケッチ74" along normal blind 3
work_plane "作業平面73" AlongDistance -33 ExtraOffset 0
sketch "スケッチ75" plane through (0, 0, -33) normal (0, 0, 1) x axis (1, 0, 0)
  line L1 (92, -65) -> (42, -65)
  line L2 (92, -40) -> (92, -65)
  line L3 (42, -40) -> (92, -40)
  line L4 (42, -65) -> (42, -40)
  line L5 (56.5, -59.7) -> (48.5, -59.7)
  line L6 (56.5, -56.3) -> (56.5, -59.7)
  line L7 (48.5, -56.3) -> (56.5, -56.3)
  line L8 (48.5, -59.7) -> (48.5, -56.3)
  line L9 (56.5, -48.7) -> (48.5, -48.7)
  line L10 (56.5, -45.3) -> (56.5, -48.7)
  line L11 (48.5, -45.3) -> (56.5, -45.3)
  line L12 (48.5, -48.7) -> (48.5, -45.3)
extrude "押し出し93" new body sketch "スケッチ75" along normal blind 3
work_plane "作業平面74" AlongDistance -34 ExtraOffset 0
sketch "スケッチ76" plane through (0, 0, -34) normal (0, 0, 1) x axis (1, 0, 0)
  line L1 (-48.5, -38.7) -> (-56.5, -38.7)
  line L2 (-48.5, -35.3) -> (-48.5, -38.7)
  line L3 (-56.5, -35.3) -> (-48.5, -35.3)
  line L4 (-56.5, -38.7) -> (-56.5, -35.3)
  line L5 (-48.5, -25.7) -> (-56.5, -25.7)
  line L6 (-48.5, -22.3) -> (-48.5, -25.7)
  line L7 (-56.5, -22.3) -> (-48.5, -22.3)
  line L8 (-56.5, -25.7) -> (-56.5, -22.3)
work_plane "作業平面75" AlongDistance -34 ExtraOffset 0
sketch "スケッチ77" plane through (0, 0, -34) normal (0, 0, 1) x axis (1, 0, 0)
  line L1 (56.5, -59.7) -> (48.5, -59.7)
  line L2 (56.5, -56.3) -> (56.5, -59.7)
  line L3 (48.5, -56.3) -> (56.5, -56.3)
  line L4 (48.5, -59.7) -> (48.5, -56.3)
  line L5 (56.5, -48.7) -> (48.5, -48.7)
  line L6 (56.5, -45.3) -> (56.5, -48.7)
  line L7 (48.5, -45.3) -> (56.5, -45.3)
  line L8 (48.5, -48.7) -> (48.5, -45.3)
work_plane "作業平面76" AlongDistance -19 ExtraOffset 0
sketch "スケッチ78" plane through (0, -19, 0) normal (0, 1, 0) x axis (1, 0, 0)
  circle C1 centre (-25, -2.8) radius 1.5
extrude "押し出し96" new body sketch "スケッチ78" along normal blind 2
work_plane "作業平面77" AlongDistance -19 ExtraOffset 0
sketch "スケッチ79" plane through (0, -19, 0) normal (0, 1, 0) x axis (1, 0, 0)
  circle C1 centre (26, -2.8) radius 1.5
work_plane "作業平面78" AlongDistance -68 ExtraOffset 0
sketch "スケッチ80" plane through (0, 0, -68) normal (0, 0, 1) x axis (1, 0, 0)
  line L1 (54, -76) -> (-54, -76)
  line L2 (54, 76) -> (54, -76)
  line L3 (-54, 76) -> (54, 76)
  line L4 (-54, -76) -> (-54, 76)
  line L5 (49, -71) -> (-49, -71)
  line L6 (49, 71) -> (49, -71)
  line L7 (-49, 71) -> (49, 71)
  line L8 (-49, -71) -> (-49, 71)
extrude "押し出し98" new body sketch "スケッチ80" along normal blind 48
work_plane "作業平面79" AlongDistance -34 ExtraOffset 0
sketch "スケッチ81" plane through (0, 0, -34) normal (0, 0, 1) x axis (1, 0, 0)
  line L1 (-48.5, -38.7) -> (-56.5, -38.7)
  line L2 (-48.5, -35.3) -> (-48.5, -38.7)
  line L3 (-56.5, -35.3) -> (-48.5, -35.3)
  line L4 (-56.5, -38.7) -> (-56.5, -35.3)
  line L5 (-48.5, -25.7) -> (-56.5, -25.7)
  line L6 (-48.5, -22.3) -> (-48.5, -25.7)
  line L7 (-56.5, -22.3) -> (-48.5, -22.3)
  line L8 (-56.5, -25.7) -> (-56.5, -22.3)
  line L9 (56.5, -59.7) -> (48.5, -59.7)
  line L10 (56.5, -56.3) -> (56.5, -59.7)
  line L11 (48.5, -56.3) -> (56.5, -56.3)
  line L12 (48.5, -59.7) -> (48.5, -56.3)
  line L13 (56.5, -48.7) -> (48.5, -48.7)
  line L14 (56.5, -45.3) -> (56.5, -48.7)
  line L15 (48.5, -45.3) -> (56.5, -45.3)
  line L16 (48.5, -48.7) -> (48.5, -45.3)
extrude "押し出し99" cut sketch "スケッチ81" profile of L9 L10 L11 L12 along normal blind 16
work_plane "作業平面80" AlongDistance -34 ExtraOffset 0
sketch "スケッチ82" plane through (0, 0, -34) normal (0, 0, 1) x axis (1, 0, 0)
  line L1 (-48.5, -38.7) -> (-56.5, -38.7)
  line L2 (-48.5, -35.3) -> (-48.5, -38.7)
  line L3 (-56.5, -35.3) -> (-48.5, -35.3)
  line L4 (-56.5, -38.7) -> (-56.5, -35.3)
  line L5 (-48.5, -25.7) -> (-56.5, -25.7)
  line L6 (-48.5, -22.3) -> (-48.5, -25.7)
  line L7 (-56.5, -22.3) -> (-48.5, -22.3)
  line L8 (-56.5, -25.7) -> (-56.5, -22.3)
  line L9 (56.5, -59.7) -> (48.5, -59.7)
  line L10 (56.5, -56.3) -> (56.5, -59.7)
  line L11 (48.5, -56.3) -> (56.5, -56.3)
  line L12 (48.5, -59.7) -> (48.5, -56.3)
  line L13 (56.5, -48.7) -> (48.5, -48.7)
  line L14 (56.5, -45.3) -> (56.5, -48.7)
  line L15 (48.5, -45.3) -> (56.5, -45.3)
  line L16 (48.5, -48.7) -> (48.5, -45.3)
extrude "押し出し100" cut sketch "スケッチ82" profile of L1 L2 L3 L4 along normal blind 16
extrude "押し出し101" cut sketch "スケッチ82" profile of L9 L10 L11 L12 along normal blind 16
extrude "押し出し102" cut sketch "スケッチ82" profile of L5 L6 L7 L8 along normal blind 16
extrude "押し出し103" cut sketch "スケッチ82" profile of L13 L14 L15 L16 along normal blind 16
work_plane "作業平面81" AlongDistance -20 ExtraOffset 0
sketch "スケッチ83" plane through (0, 0, -20) normal (0, 0, 1) x axis (1, 0, 0)
  line L1 (54, -76) -> (-54, -76)
  line L2 (54, -61.5) -> (54, -76)
  line L3 (-54, -61.5) -> (54, -61.5)
  line L4 (-54, -76) -> (-54, -61.5)
  line L5 (-33, -71) -> (-47, -71)
  line L6 (-33, -66.6) -> (-33, -71)
  line L7 (-47, -66.6) -> (-33, -66.6)
  line L8 (-47, -71) -> (-47, -66.6)
  line L9 (47, -71) -> (33, -71)
  line L10 (47, -66.6) -> (47, -71)
  line L11 (33, -66.6) -> (47, -66.6)
  line L12 (33, -71) -> (33, -66.6)
extrude "押し出し104" new body sketch "スケッチ83" along normal blind 20
work_plane "作業平面82" AlongDistance -41 ExtraOffset 0
sketch "スケッチ84" plane through (0, -41, 0) normal (0, 1, 0) x axis (1, 0, 0)
  circle C1 centre (26, -2.8) radius 1.5
extrude "押し出し105" new body sketch "スケッチ84" along normal blind 2
copy_paste_bodies "CutPasteBodies1"
copy_paste_bodies "CutPasteBodies1"
copy_paste_bodies "CutPasteBodies1"
copy_paste_bodies "CutPasteBodies1"
copy_paste_bodies "CutPasteBodies1"
copy_paste_bodies "CutPasteBodies1"
copy_paste_bodies "CutPasteBodies1"
copy_paste_bodies "CutPasteBodies1"
copy_paste_bodies "CutPasteBodies1"
copy_paste_bodies "CutPasteBodies1"
copy_paste_bodies "CutPasteBodies1"
copy_paste_bodies "CutPasteBodies1"
copy_paste_bodies "CutPasteBodies1"
copy_paste_bodies "CutPasteBodies1"
copy_paste_bodies "CutPasteBodies1"
copy_paste_bodies "CutPasteBodies1"
copy_paste_bodies "CutPasteBodies1"
copy_paste_bodies "CutPasteBodies1"
copy_paste_bodies "CutPasteBodies1"
copy_paste_bodies "CutPasteBodies1"
copy_paste_bodies "CutPasteBodies1"
copy_paste_bodies "CutPasteBodies1"
copy_paste_bodies "CutPasteBodies1"
copy_paste_bodies "CutPasteBodies1"
copy_paste_bodies "CutPasteBodies1"
copy_paste_bodies "CutPasteBodies1"
copy_paste_bodies "CutPasteBodies1"
copy_paste_bodies "CutPasteBodies2"
copy_paste_bodies "CutPasteBodies3"
copy_paste_bodies "CutPasteBodies4"
work_plane "作業平面1" AlongDistance 3 ExtraOffset 0
sketch "スケッチ1" plane through (0, 0, 3) normal (0, 0, 1) x axis (1, 0, 0)
  line L1 (10, -30) -> (-10, -30)
  line L2 (10, -10) -> (10, -30)
  line L3 (-10, -10) -> (10, -10)
  line L4 (-10, -30) -> (-10, -10)
  circle C1 centre (25, -20) radius 7
  circle C2 centre (-25, -42) radius 7
  circle C3 centre (0, -42) radius 7
extrude "押し出し1" cut sketch "スケッチ1" against normal blind 14 (magnitude of "-( 14.00 mm )")
work_plane "作業平面1" AlongDistance -5 ExtraOffset 0
sketch "スケッチ1" plane through (0, 0, -5) normal (0, 0, 1) x axis (1, 0, 0)
  line L1 (-40, -27) -> (-76, -27)
  line L2 (-40, -9) -> (-40, -27)
  line L3 (-76, -9) -> (-40, -9)
  line L4 (-76, -27) -> (-76, -9)
  line L5 (-45.25, -24.75) -> (-70.75, -24.75)
  line L6 (-45.25, -11.25) -> (-45.25, -24.75)
  line L7 (-70.75, -11.25) -> (-45.25, -11.25)
  line L8 (-70.75, -24.75) -> (-70.75, -11.25)
  line L9 (-55, -13) -> (-61, -13)
  line L10 (-55, -7) -> (-55, -13)
  line L11 (-61, -7) -> (-55, -7)
  line L12 (-61, -13) -> (-61, -7)
  line L13 (76, -49.5) -> (40, -49.5)
  line L14 (76, -31.5) -> (76, -49.5)
  line L15 (40, -31.5) -> (76, -31.5)
  line L16 (40, -49.5) -> (40, -31.5)
  line L17 (70.75, -47.25) -> (45.25, -47.25)
  line L18 (70.75, -33.75) -> (70.75, -47.25)
  line L19 (45.25, -33.75) -> (70.75, -33.75)
  line L20 (45.25, -47.25) -> (45.25, -33.75)
  line L21 (61, -35.5) -> (55, -35.5)
  line L22 (61, -29.5) -> (61, -35.5)
  line L23 (55, -29.5) -> (61, -29.5)
  line L24 (55, -35.5) -> (55, -29.5)
  circle C1 centre (-72, -18) radius 1.3
  circle C2 centre (-44, -18) radius 1.3
  circle C3 centre (44, -40.5) radius 1.3
  circle C4 centre (72, -40.5) radius 1.3
extrude "押し出し1" new body sketch "スケッチ1" along normal blind 2 bodies "SG90 mount Call", "SG90 mount End"
work_plane "作業平面2" AlongDistance 3 ExtraOffset 0
sketch "スケッチ2" plane through (0, 0, 3) normal (0, 0, 1) x axis (1, 0, 0)
  line L1 (-15, -52) -> (-35, -52)
  line L2 (-15, -32) -> (-15, -52)
  line L3 (-35, -32) -> (-15, -32)
  line L4 (-35, -52) -> (-35, -32)
extrude "押し出し2" cut sketch "スケッチ2" against normal blind 14 (magnitude of "-( 14.00 mm )")
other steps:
base_feature "基準フィーチャ1"
base_feature "基準フィーチャ1"
base_feature "基準フィーチャ1"
base_feature "基準フィーチャ1"
base_feature "基準フィーチャ1"
base_feature "基準フィーチャ1"
base_feature "基準フィーチャ1"
base_feature "基準フィーチャ1"
base_feature "基準フィーチャ1"
base_feature "基準フィーチャ1"
base_feature "基準フィーチャ1"
base_feature "基準フィーチャ1"
base_feature "基準フィーチャ1"
base_feature "基準フィーチャ1"
base_feature "基準フィーチャ1"
base_feature "基準フィーチャ1"
base_feature "基準フィーチャ1"
base_feature "基準フィーチャ1"
base_feature "基準フィーチャ1"
base_feature "基準フィーチャ1"
base_feature "基準フィーチャ1"
base_feature "基準フィーチャ1"
base_feature "基準フィーチャ1"
base_feature "基準フィーチャ1"
base_feature "基準フィーチャ1"
base_feature "基準フィーチャ1"
base_feature "基準フィーチャ1"
base_feature "基準フィーチャ2"
base_feature "基準フィーチャ3"
base_feature "基準フィーチャ4"
create_component "CreateComponent1"
create_component "CreateComponent1"
reparent_decal "デカールを再ペアレント化1"
remove_body "RemoveBody1"
create_component "CreateComponent2"
reparent_decal "デカールを再ペアレント化2"
remove_body "RemoveBody2"
create_component "CreateComponent3"
reparent_decal "デカールを再ペアレント化3"
remove_body "RemoveBody3"
create_component "CreateComponent4"
reparent_decal "デカールを再ペアレント化4"
remove_body "RemoveBody4"
create_component "CreateComponent5"
reparent_decal "デカールを再ペアレント化5"
remove_body "RemoveBody5"
create_component "CreateComponent6"
reparent_decal "デカールを再ペアレント化6"
remove_body "RemoveBody6"
create_component "CreateComponent7"
reparent_decal "デカールを再ペアレント化7"
remove_body "RemoveBody7"
create_component "CreateComponent8"
reparent_decal "デカールを再ペアレント化8"
remove_body "RemoveBody8"
create_component "CreateComponent9"
reparent_decal "デカールを再ペアレント化9"
remove_body "RemoveBody9"
create_component "CreateComponent10"
reparent_decal "デカールを再ペアレント化10"
remove_body "RemoveBody10"
create_component "CreateComponent11"
reparent_decal "デカールを再ペアレント化11"
remove_body "RemoveBody11"
create_component "CreateComponent12"
reparent_decal "デカールを再ペアレント化12"
remove_body "RemoveBody12"
create_component "CreateComponent13"
reparent_decal "デカールを再ペアレント化13"
remove_body "RemoveBody13"
create_component "CreateComponent14"
reparent_decal "デカールを再ペアレント化14"
remove_body "RemoveBody14"
create_component "CreateComponent15"
reparent_decal "デカールを再ペアレント化15"
remove_body "RemoveBody15"
create_component "CreateComponent16"
reparent_decal "デカールを再ペアレント化16"
remove_body "RemoveBody16"
create_component "CreateComponent17"
reparent_decal "デカールを再ペアレント化17"
remove_body "RemoveBody17"
create_component "CreateComponent18"
reparent_decal "デカールを再ペアレント化18"
remove_body "RemoveBody18"
create_component "CreateComponent19"
reparent_decal "デカールを再ペアレント化19"
remove_body "RemoveBody19"
create_component "CreateComponent20"
reparent_decal "デカールを再ペアレント化20"
remove_body "RemoveBody20"
create_component "CreateComponent21"
reparent_decal "デカールを再ペアレント化21"
remove_body "RemoveBody21"
create_component "CreateComponent22"
reparent_decal "デカールを再ペアレント化22"
remove_body "RemoveBody22"
create_component "CreateComponent23"
reparent_decal "デカールを再ペアレント化23"
remove_body "RemoveBody23"
create_component "CreateComponent24"
reparent_decal "デカールを再ペアレント化24"
remove_body "RemoveBody24"
create_component "CreateComponent25"
reparent_decal "デカールを再ペアレント化25"
remove_body "RemoveBody25"
create_component "CreateComponent26"
reparent_decal "デカールを再ペアレント化26"
remove_body "RemoveBody26"
create_component "CreateComponent27"
reparent_decal "デカールを再ペアレント化27"
remove_body "RemoveBody27"
reparent_decal "デカールを再ペアレント化28"
remove_body "RemoveBody28"
reparent_decal "デカールを再ペアレント化29"
remove_body "RemoveBody29"
reparent_decal "デカールを再ペアレント化30"
remove_body "RemoveBody30"
named bodies: "SG90 mount Call", "SG90 mount End"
